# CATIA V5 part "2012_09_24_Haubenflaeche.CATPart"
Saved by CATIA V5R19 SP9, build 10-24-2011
Part number: Leuchte_lang.SLDPRT
Material "Brushed metal 1": density 7860 kg/m3, Young's modulus 2e+11 Pa, Poisson ratio 0.266
Bounding box of the stored display mesh (mm): x 0 to 62, y -12.253 to 12.253, z 0 to 19.481
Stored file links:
  D:\Daten\downloadv5\2012_09_24_Haubenflaeche.CATPart
  \\bitter.at\Bitter_Daten\Catia_V5\Umgebungen\BMW_R19_64bit\win_b64\startup\materials\Catalog.CATMaterial
  \\bitter.at\Bitter_Daten\Catia_V5\Umgebungen\BMW_R19_64bit\win_b64\startup\materials\brushed_metal1.jpg

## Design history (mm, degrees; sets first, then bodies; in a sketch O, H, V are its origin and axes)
Set1
  DatumSurface1 "Join"
  Plane1: type Offset, RefPlane yz-plane, Offset 18.5
  Sketch1 "Skizze.1" on Plane1, origin (18.5, 0, 0), H (0, 1, 0), V (0, 0, 1)
    intersected arc E1 centre (10117.2437, -346.7624) radius 10134.8307 from (-11.0962, 15.8997) to (-11.5484, 3.0421) ccw from face of DatumSurface1
    intersected arc E2 centre (-10117.2437, -346.7624) radius 10134.8307 from (11.5484, 3.0421) to (11.0962, 15.8997) ccw from face of DatumSurface1
    axis line L1 (0, 0) -> (0, 19.3)
    point P5 (0, 19.3)
    arc A1 centre (0, -0.5052) radius 19.8052 from (-11.0962, 15.8997) to (11.0962, 15.8997) cw
    length L1 = 19.3
    vertical: L1 V
    coincidence: A1 P5
  Sketch2 on zx-plane, origin (0, 0, 0), H (-1, 0, 0), V (0, 0, 1)
    reference intersected point E2 (-18.5, 19.3) from Sketch1.A1
    arc A1 centre (-23.28, -42.1413) radius 61.6269 from (-60.0716, 7.2981) to (-0.7, 15.2) cw
    coincidence: A1 E2
  Boundary1: Boundary edge of DatumSurface1
  Boundary2: Boundary edge of DatumSurface1
  Extrude1: Lim1 20, Lim2 20, Element1 Sketch2
  Loft1: Sections (Boundary2; Sketch2), EndSectionTangent Extrude1, Guides Sketch1
  Loft2: Sections (Boundary1; Sketch2), EndSectionTangent Extrude1, Guides Sketch1
  Join1: Elements (Loft1; Loft2)
  Join2: Elements (Join1; DatumSurface1)
Body1 (main body)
